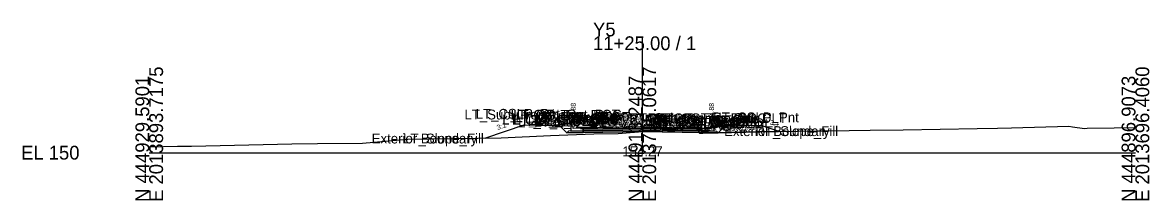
# Model space of a CAD drawing. Extents: x -26 to 203, y -10 to 4517.
# Drawn here: x -25.7 to 202.8, y 2490.3 to 2526.4 of the extents above; entities that cross this region are included whole.
import ezdxf

# ---------------------------------------------------------------- set-up
doc = ezdxf.new("R2010")
doc.units = 0
for name, color, linetype in [('Default', 7, 'Continuous'), ('Exist Cross Section Cell', 7, 'Continuous'), ('Exist XS Center Line Elevation Label', 7, 'Continuous'), ('Exist XS Ground Line', 7, 'Continuous'), ('Prop CMT Conc Surface', 7, 'Continuous'), ('Prop CMT Concrete Structures', 7, 'Continuous'), ('Prop CMT Pvmt Course 1', 7, 'Continuous'), ('Prop CMT Pvmt Course 1 CG', 7, 'Continuous'), ('Prop CMT Pvmt Course 2', 7, 'Continuous'), ('Prop CMT Pvmt Course 3', 7, 'Continuous'), ('Prop CMT Pvmt Surface', 7, 'Continuous'), ('Prop CMT Slope Grass', 7, 'Continuous'), ('Prop CMT Subgrade Earthwork', 7, 'Continuous'), ('Prop XS Earthwork Shape', 7, 'Continuous'), ('Prop XS Hydro Elevations', 7, 'Continuous'), ('Prop XS SE Text', 7, 'Continuous'), ('Prop XS Side Slope Text', 7, 'Continuous'), ('Scratch_Level_0', 7, 'Continuous')]:
    doc.layers.add(name, color=color, linetype=linetype)

msp = doc.modelspace()

# ---------------------------------------------------------------- linework, layer by layer
at = {"layer": 'Exist Cross Section Cell'}
for p, q in [((100, 2500), (100, 2523.6)), ((0, 2500), (100, 2500)), ((100, 2500), (200, 2500))]:
    msp.add_line(p, q, dxfattribs=at)
at = {"layer": 'Exist XS Ground Line'}
msp.add_lwpolyline([(0, 2501.22), (5.74, 2501.3), (8.54, 2501.33), (28.9, 2501.79), (34.14, 2501.88), (43.22, 2501.91), (52.47, 2502.75), (71.35, 2503.01), (81.39, 2503.46), (90.13, 2503.84), (95.12, 2503.86), (100, 2504.27), (111.02, 2505.21), (111.6, 2503.97), (112.28, 2503.97), (126.74, 2504.28), (127.59, 2504.29), (135.69, 2504.4), (137.71, 2504.43), (146.22, 2504.58), (152.87, 2504.64), (167.88, 2504.91), (172, 2505), (174.88, 2505.04), (186.48, 2505.35), (187.23, 2505.25), (189.67, 2504.93), (190.22, 2504.94), (195.67, 2505.02), (200, 2505.12)], dxfattribs=at)
at = {"layer": 'Prop CMT Conc Surface'}
for points in [[(86, 2504.88), (86, 2505.38), (85.5, 2505.38)], [(88, 2505), (86, 2504.88)], [(112.03, 2505), (114.03, 2504.88)], [(114.03, 2504.88), (114.03, 2505.38), (114.53, 2505.38)]]:
    msp.add_lwpolyline(points, dxfattribs=at)
at = {"layer": 'Prop CMT Concrete Structures'}
for points in [[(88, 2505), (86, 2504.88), (86, 2505.38), (85.5, 2505.38)], [(85.5, 2505.38), (85.5, 2504.36), (88, 2504.41)], [(88, 2504.41), (88, 2505)], [(112.03, 2505), (114.03, 2504.88), (114.03, 2505.38), (114.53, 2505.38)], [(114.53, 2505.38), (114.53, 2504.36), (112.03, 2504.41)], [(112.03, 2504.41), (112.03, 2505)]]:
    msp.add_lwpolyline(points, dxfattribs=at)
at = {"layer": 'Prop CMT Pvmt Course 1'}
for points in [[(100, 2505.24), (88, 2505)], [(88, 2505), (88, 2504.75)], [(88, 2504.75), (100, 2504.99)], [(100, 2504.99), (100, 2505.24)], [(100, 2505.24), (112.03, 2505)], [(100, 2504.99), (100, 2505.24)], [(112.03, 2504.75), (100, 2504.99)], [(112.03, 2505), (112.03, 2504.75)]]:
    msp.add_lwpolyline(points, dxfattribs=at)
msp.add_lwpolyline([(100, 2504.99), (100, 2505.11), (100, 2505.11), (100, 2504.99)], close=True, dxfattribs=at)
msp.add_lwpolyline([(100, 2504.99), (100, 2505.11), (100, 2505.11), (100, 2504.99)], close=True, dxfattribs=at)
at = {"layer": 'Prop CMT Pvmt Course 1 CG'}
for points in [[(88, 2504.41), (85, 2504.35), (84.66, 2504.01)], [(84.66, 2504.01), (88, 2504.08)], [(88, 2504.08), (88, 2504.41)], [(112.03, 2504.41), (115.03, 2504.35), (115.37, 2504.01)], [(112.03, 2504.08), (112.03, 2504.41)], [(115.37, 2504.01), (112.03, 2504.08)]]:
    msp.add_lwpolyline(points, dxfattribs=at)
at = {"layer": 'Prop CMT Pvmt Course 2'}
for points in [[(100, 2504.99), (88, 2504.75)], [(88, 2504.75), (88, 2504.41)], [(100, 2504.65), (100, 2504.99)], [(100, 2504.65), (100, 2504.99)], [(100, 2504.99), (112.03, 2504.75)], [(112.03, 2504.75), (112.03, 2504.41)], [(88, 2504.41), (100, 2504.65)], [(112.03, 2504.41), (100, 2504.65)]]:
    msp.add_lwpolyline(points, dxfattribs=at)
at = {"layer": 'Prop CMT Pvmt Course 3'}
for points in [[(100, 2504.65), (88, 2504.41)], [(88, 2504.41), (88, 2504.08)], [(88, 2504.08), (100, 2504.32)], [(100, 2504.32), (100, 2504.65)], [(100, 2504.65), (112.03, 2504.41)], [(100, 2504.32), (100, 2504.65)], [(112.03, 2504.08), (100, 2504.32)], [(112.03, 2504.41), (112.03, 2504.08)]]:
    msp.add_lwpolyline(points, dxfattribs=at)
at = {"layer": 'Prop CMT Pvmt Surface'}
for points in [[(100, 2505.24), (88, 2505)], [(100, 2505.24), (112.03, 2505)]]:
    msp.add_lwpolyline(points, dxfattribs=at)
at = {"layer": 'Prop CMT Slope Grass'}
for points in [[(85.5, 2505.38), (76, 2505.57), (68.2, 2502.97)], [(114.53, 2505.38), (124.03, 2505.57), (127.86, 2504.29)]]:
    msp.add_lwpolyline(points, dxfattribs=at)
at = {"layer": 'Prop CMT Subgrade Earthwork'}
for points in [[(88, 2504.08), (84.66, 2504.01), (83.25, 2505.42)], [(112.03, 2504.08), (115.37, 2504.01), (116.78, 2505.42)], [(100, 2504.32), (88, 2504.08)], [(100, 2504.32), (112.03, 2504.08)]]:
    msp.add_lwpolyline(points, dxfattribs=at)
at = {"layer": 'Prop XS Earthwork Shape'}
for points in [[(100, 2504.27), (100.45, 2504.31), (100, 2504.32), (88, 2504.08), (84.66, 2504.01), (83.25, 2505.42), (76, 2505.57), (68.2, 2502.97), (71.35, 2503.01), (81.39, 2503.46), (90.13, 2503.84), (95.12, 2503.86)], [(109.15, 2505.05), (111.11, 2505.01), (111.55, 2504.09), (100.45, 2504.31)], [(109.15, 2505.05), (111.02, 2505.21), (111.11, 2505.01)], [(124.03, 2505.57), (127.86, 2504.29), (127.59, 2504.29), (126.74, 2504.28), (115.39, 2504.04), (116.78, 2505.42)], [(112.03, 2504.08), (114.83, 2504.02), (112.28, 2503.97), (111.6, 2503.97), (111.55, 2504.09)], [(115.37, 2504.01), (115.39, 2504.04), (114.83, 2504.02)]]:
    msp.add_lwpolyline(points, close=True, dxfattribs=at)

# ---------------------------------------------------------------- texts
at = {"layer": 'Default'}
msp.add_text('-', height=0.0001, dxfattribs=at).set_placement((0, 2500))
at = {"layer": 'Exist Cross Section Cell'}
for s, p in [('Y5', (90, 2523.6)), ('11+25.00 / 1', (90, 2520.8)), ('EL 150', (-26, 2498.6))]:
    msp.add_text(s, height=2.8, dxfattribs=at).set_placement(p)
for s, p in [('E 2013893.7175', (2.8, 2490)), ('E 2013795.0617', (102.8, 2490)), ('E 2013696.4060', (202.8, 2490)), ('N 444929.5901', (0, 2490)), ('N 444913.2487', (100, 2490)), ('N 444896.9073', (200, 2490))]:
    msp.add_text(s, height=2.8, rotation=90, dxfattribs=at).set_placement(p)
at = {"layer": 'Exist XS Center Line Elevation Label'}
msp.add_text('154.27', height=2, dxfattribs=at).set_placement((95.94, 2499.27))
at = {"layer": 'Prop XS Hydro Elevations'}
for p in [(86.5, 2505.86), (114.53, 2505.86)]:
    msp.add_text('154.88', height=1, rotation=90, dxfattribs=at).set_placement(p)
at = {"layer": 'Prop XS SE Text'}
for rotation, p in [(1.1458, (92.35, 2506)), (358.8542, (104.29, 2506.09))]:
    msp.add_text('0.020', height=1, rotation=rotation, dxfattribs=at).set_placement(p)
at = {"layer": 'Prop XS Side Slope Text'}
for rotation, p in [(18.4332, (70.66, 2504.6)), (341.5667, (125.78, 2505.76))]:
    msp.add_text('3:1', height=1, rotation=rotation, dxfattribs=at).set_placement(p)
at = {"layer": 'Scratch_Level_0'}
for s, p in [('LT_Sub_Trench_Out_DLT', (63.92, 2506.74)), ('LT_CSLP_Pnt', (66.2, 2506.88)), ('LT_CG1_Shelf_Out', (71.58, 2505.71)), ('LT_CG_Top_Face', (73.29, 2506.69)), ('LT_CG_Top_BOC', (73.81, 2506.69)), ('LT_CG_Bot_BOC', (73.84, 2505.7)), ('LT_CG_Top_Gut', (74.26, 2506.19)), ('LT_Sub_OEOP', (74.81, 2505.39)), ('LT_CG_Bot_IE', (77.94, 2505.65)), ('LT_Sub_OEOT', (78.1, 2505.31)), ('LT_PV2_OEOT', (78.2, 2505.98)), ('LT_PV3_OEOT', (78.2, 2505.65)), ('LT_PV1_OEOT', (78.77, 2506.23)), ('RT_Sub_OEEOP', (89.19, 2505.05)), ('LT_Sub_OEEOP', (89.24, 2505.05)), ('RT_PV2_OEEOP', (89.28, 2505.72)), ('RT_PV3_OEEOP', (89.28, 2505.39)), ('LT_PV2_OEEOP', (89.33, 2505.72)), ('LT_PV3_OEEOP', (89.33, 2505.39)), ('RT_PV1_OEEOP', (89.85, 2505.85)), ('LT_PV1_OEEOP', (89.9, 2505.85)), ('RT_PV2_IEEOP', (89.93, 2505.72)), ('LT_PV2_IEEOP', (89.98, 2505.72)), ('RT_PV1_IEEOP', (90.5, 2505.85)), ('LT_PV1_IEEOP', (90.54, 2505.85)), ('PV2_PGL', (93.93, 2505.72)), ('PV1_PGL', (94.5, 2505.97)), ('RT_Sub_Trench_Out_DLT', (97.34, 2506.01)), ('RT_CG_Top_Face', (101.27, 2505.97)), ('RT_CG1_Shelf_Out', (101.56, 2504.94)), ('RT_CG_Bot_IE', (101.92, 2505.03)), ('RT_PV2_OEOT', (102.18, 2505.36)), ('RT_PV3_OEOT', (102.18, 2505.03)), ('RT_CG_Top_Gut', (102.24, 2505.47)), ('RT_PV1_OEOT', (102.75, 2505.61)), ('RT_CG_Top_BOC', (102.79, 2505.97)), ('RT_CSLP_Pnt', (114.18, 2506.16)), ('RT_Sub_OEOT', (102.09, 2504.69)), ('RT_CG_Bot_BOC', (102.82, 2504.95)), ('RT_Sub_OEOP', (105.46, 2504.59)), ('Exterior Boundary', (116.58, 2503.37)), ('RT_Slope_Fill', (122.91, 2503.37)), ('Exterior Boundary', (45.12, 2501.87)), ('LT_Slope_Fill', (51.5, 2501.87))]:
    msp.add_text(s, height=2, dxfattribs=at).set_placement(p)

doc.saveas('drawing.dxf')
